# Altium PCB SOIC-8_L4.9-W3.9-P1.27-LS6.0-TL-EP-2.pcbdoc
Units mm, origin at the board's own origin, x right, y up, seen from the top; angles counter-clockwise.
Board outline 19.66 x 18.45 mm, 2 copper layers (Top Layer, Bottom Layer), stack 0 mm thick; 1 components, 0 nets, 9 pads, 0 vias.
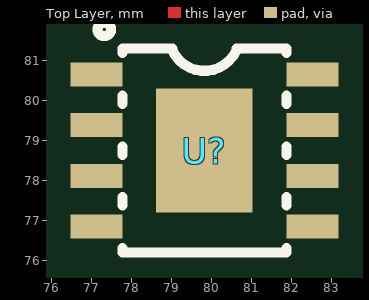
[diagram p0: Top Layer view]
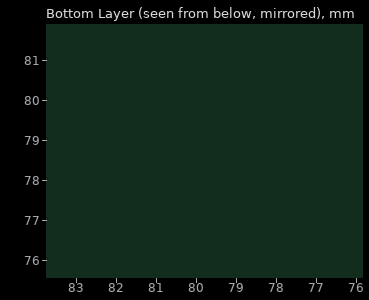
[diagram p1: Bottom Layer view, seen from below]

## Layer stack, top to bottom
Top Layer: signal copper (thickness not stored)
Bottom Layer: signal copper (thickness not stored)

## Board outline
89.51,69.85 69.85,69.85 69.85,88.3 89.51,88.3

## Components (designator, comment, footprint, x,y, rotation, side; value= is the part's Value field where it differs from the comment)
U? "" SOIC-8_L4.9-W3.9-P1.27-LS6.0-TL-EP-2 79.81,78.75 r0 top

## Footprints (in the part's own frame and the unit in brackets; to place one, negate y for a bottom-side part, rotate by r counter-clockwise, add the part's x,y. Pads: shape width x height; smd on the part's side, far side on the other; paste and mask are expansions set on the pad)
SOIC-8_L4.9-W3.9-P1.27-LS6.0-TL-EP-2 [mm]
  rect 1.3x0.6 smd: 1(-2.7,1.905) 2(-2.7,0.635) 3(-2.7,-0.635) 4(-2.7,-1.905) 5(2.7,-1.905) 6(2.7,-0.635) 7(2.7,0.635) 8(2.7,1.905)
  rect 2.41x3.1 smd: 9(0,0)
  silkscreen extent -2.67,-2.55 2.05,3.2

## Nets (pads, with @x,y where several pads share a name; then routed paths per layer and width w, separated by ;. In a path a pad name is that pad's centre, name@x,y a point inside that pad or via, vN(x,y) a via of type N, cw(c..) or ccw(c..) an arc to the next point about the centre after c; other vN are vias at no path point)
pads on no net: U?.1 U?.2 U?.3 U?.4 U?.5 U?.6 U?.7 U?.8 U?.9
